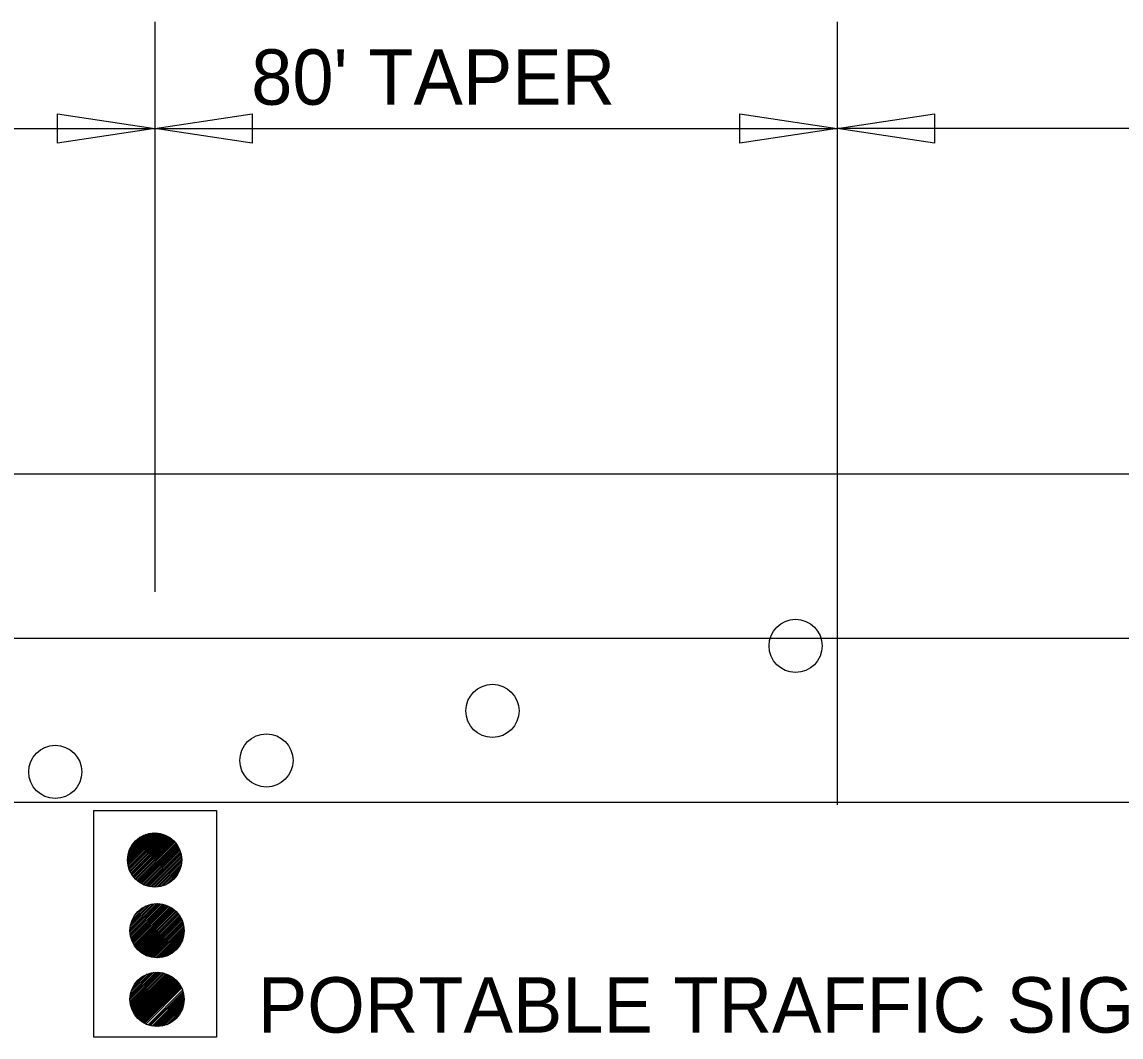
# Model space of a CAD drawing. Extents: x 1930579 to 1939784, y 596179 to 597522.
# Drawn here: x 1938170.6 to 1938289.6, y 596880.5 to 596990.5 of the extents above; entities that cross this region are included whole.
import ezdxf

# ---------------------------------------------------------------- set-up
doc = ezdxf.new("R2010")
doc.units = 0
doc.layers.add('Default', color=7, linetype='Continuous')

msp = doc.modelspace()

# ---------------------------------------------------------------- linework, layer by layer
at = {"layer": 'Default'}
for p, q in [((1938184.94, 596990.46), (1938184.94, 596928.7)), ((1938258.87, 596990.46), (1938258.87, 596928.7)), ((1938174.39, 596977.33), (1938174.39, 596980.5)), ((1938174.39, 596980.5), (1938184.94, 596978.92)), ((1938184.94, 596978.92), (1938195.48, 596980.5)), ((1938195.48, 596980.5), (1938195.48, 596977.33)), ((1938248.33, 596977.33), (1938248.33, 596980.5)), ((1938248.33, 596980.5), (1938258.87, 596978.92)), ((1938258.87, 596978.92), (1938269.42, 596980.5)), ((1938269.42, 596980.5), (1938269.42, 596977.33)), ((1938134.27, 596978.92), (1938184.94, 596978.92)), ((1938184.94, 596978.92), (1938174.39, 596977.33)), ((1938184.94, 596978.92), (1938258.87, 596978.92)), ((1938195.48, 596977.33), (1938184.94, 596978.92)), ((1938258.87, 596978.92), (1938248.33, 596977.33)), ((1938269.42, 596977.33), (1938258.87, 596978.92)), ((1938703.26, 596978.92), (1938258.87, 596978.92)), ((1938258.87, 596957.84), (1938258.87, 596905.62)), ((1937601.26, 596941.48), (1938703.26, 596941.48)), ((1937499.1, 596923.69), (1938703.26, 596923.69)), ((1937601.26, 596905.9), (1938703.26, 596905.9)), ((1938181.98, 596899.52), (1938185.06, 596902.59)), ((1938181.98, 596899.69), (1938184.88, 596902.59)), ((1938181.99, 596899.35), (1938185.22, 596902.58)), ((1938181.99, 596899.88), (1938184.69, 596902.58)), ((1938182.01, 596900.09), (1938184.48, 596902.56)), ((1938182.02, 596899.19), (1938185.38, 596902.56)), ((1938182.04, 596899.04), (1938185.54, 596902.53)), ((1938182.05, 596900.31), (1938184.26, 596902.52)), ((1938182.08, 596898.89), (1938185.68, 596902.49)), ((1938182.12, 596898.75), (1938185.82, 596902.45)), ((1938182.12, 596900.56), (1938184.01, 596902.45)), ((1938182.17, 596898.62), (1938185.96, 596902.41)), ((1938182.22, 596898.49), (1938186.08, 596902.35)), ((1938182.24, 596900.86), (1938183.72, 596902.34)), ((1938182.28, 596898.36), (1938186.21, 596902.3)), ((1938182.34, 596898.24), (1938186.33, 596902.23)), ((1938182.4, 596898.13), (1938186.44, 596902.17)), ((1938182.45, 596901.25), (1938183.32, 596902.12)), ((1938182.47, 596898.02), (1938186.55, 596902.1)), ((1938182.55, 596897.91), (1938186.66, 596902.02)), ((1938182.63, 596897.81), (1938186.76, 596901.95)), ((1938182.71, 596897.71), (1938186.86, 596901.86)), ((1938182.8, 596897.62), (1938186.95, 596901.78)), ((1938182.89, 596897.53), (1938187.05, 596901.69)), ((1938182.98, 596897.44), (1938187.13, 596901.59)), ((1938183.08, 596897.36), (1938187.21, 596901.49)), ((1938183.18, 596897.28), (1938187.29, 596901.39)), ((1938183.29, 596897.2), (1938187.37, 596901.28)), ((1938183.4, 596897.13), (1938187.44, 596901.17)), ((1938183.51, 596897.07), (1938187.5, 596901.06)), ((1938183.63, 596897.01), (1938187.56, 596900.94)), ((1938183.76, 596896.95), (1938187.62, 596900.82)), ((1938183.89, 596896.9), (1938187.67, 596900.69)), ((1938184.02, 596896.85), (1938187.72, 596900.55)), ((1938184.16, 596896.81), (1938187.76, 596900.41)), ((1938184.31, 596896.78), (1938187.8, 596900.27)), ((1938184.46, 596896.75), (1938187.83, 596900.11)), ((1938184.62, 596896.73), (1938187.85, 596899.95)), ((1938184.79, 596896.71), (1938187.86, 596899.79)), ((1938184.96, 596896.71), (1938187.86, 596899.61)), ((1938185.15, 596896.72), (1938187.85, 596899.42)), ((1938185.36, 596896.74), (1938187.83, 596899.21)), ((1938185.58, 596896.79), (1938187.79, 596898.99)), ((1938185.83, 596896.86), (1938187.72, 596898.74)), ((1938186.13, 596896.97), (1938187.6, 596898.44)), ((1938186.53, 596897.19), (1938187.38, 596898.05)), ((1938182.25, 596891.86), (1938185.32, 596894.93)), ((1938182.25, 596892.04), (1938185.15, 596894.93)), ((1938182.26, 596892.23), (1938184.96, 596894.93)), ((1938182.26, 596891.69), (1938185.49, 596894.92)), ((1938182.28, 596891.53), (1938185.65, 596894.9)), ((1938182.28, 596892.43), (1938184.75, 596894.9)), ((1938182.31, 596891.38), (1938185.81, 596894.87)), ((1938182.32, 596892.65), (1938184.53, 596894.86)), ((1938182.35, 596891.23), (1938185.95, 596894.83)), ((1938182.39, 596891.09), (1938186.09, 596894.79)), ((1938182.39, 596892.9), (1938184.28, 596894.79)), ((1938182.44, 596890.96), (1938186.23, 596894.75)), ((1938182.49, 596890.83), (1938186.35, 596894.69)), ((1938182.51, 596893.2), (1938183.98, 596894.68)), ((1938182.54, 596890.7), (1938186.48, 596894.64)), ((1938182.61, 596890.59), (1938186.6, 596894.58)), ((1938182.67, 596890.47), (1938186.71, 596894.51)), ((1938182.72, 596893.59), (1938183.59, 596894.46)), ((1938182.74, 596890.36), (1938186.82, 596894.44)), ((1938182.82, 596890.25), (1938186.93, 596894.37)), ((1938182.9, 596890.15), (1938187.03, 596894.29)), ((1938182.98, 596890.05), (1938187.13, 596894.2)), ((1938183.06, 596889.96), (1938187.22, 596894.12)), ((1938183.16, 596889.87), (1938187.31, 596894.03)), ((1938183.25, 596889.78), (1938187.4, 596893.93)), ((1938183.35, 596889.7), (1938187.48, 596893.83)), ((1938183.45, 596889.62), (1938187.56, 596893.73)), ((1938183.56, 596889.55), (1938187.64, 596893.63)), ((1938183.67, 596889.48), (1938187.71, 596893.51)), ((1938183.78, 596889.41), (1938187.77, 596893.4)), ((1938183.9, 596889.35), (1938187.83, 596893.28)), ((1938184.03, 596889.29), (1938187.89, 596893.16)), ((1938184.15, 596889.24), (1938187.94, 596893.03)), ((1938184.29, 596889.19), (1938187.99, 596892.89)), ((1938184.43, 596889.15), (1938188.03, 596892.75)), ((1938184.57, 596889.12), (1938188.07, 596892.61)), ((1938184.73, 596889.09), (1938188.09, 596892.46)), ((1938184.89, 596889.07), (1938188.12, 596892.3)), ((1938185.06, 596889.05), (1938188.13, 596892.13)), ((1938185.23, 596889.05), (1938188.13, 596891.95)), ((1938185.42, 596889.06), (1938188.12, 596891.76)), ((1938185.63, 596889.08), (1938188.1, 596891.55)), ((1938185.85, 596889.13), (1938188.06, 596891.33)), ((1938186.1, 596889.2), (1938187.99, 596891.08)), ((1938186.4, 596889.31), (1938187.87, 596890.79)), ((1938186.8, 596889.53), (1938187.65, 596890.39)), ((1938182.25, 596884.52), (1938185.23, 596887.5)), ((1938182.25, 596884.7), (1938185.04, 596887.49)), ((1938182.26, 596884.34), (1938185.4, 596887.49)), ((1938182.27, 596884.9), (1938184.85, 596887.48)), ((1938182.27, 596884.18), (1938185.56, 596887.47)), ((1938182.3, 596884.02), (1938185.72, 596887.45)), ((1938182.3, 596885.11), (1938184.63, 596887.44)), ((1938182.33, 596883.87), (1938185.87, 596887.42)), ((1938182.36, 596885.35), (1938184.39, 596887.39)), ((1938182.37, 596883.73), (1938186.01, 596887.38)), ((1938182.41, 596883.59), (1938186.15, 596887.33)), ((1938182.45, 596885.62), (1938184.12, 596887.3)), ((1938182.46, 596883.46), (1938186.28, 596887.28)), ((1938182.51, 596883.33), (1938186.41, 596887.23)), ((1938182.57, 596883.21), (1938186.53, 596887.17)), ((1938182.6, 596885.96), (1938183.79, 596887.14)), ((1938182.64, 596883.09), (1938186.65, 596887.11)), ((1938182.7, 596882.98), (1938186.76, 596887.04)), ((1938182.78, 596882.87), (1938186.87, 596886.97)), ((1938182.85, 596882.77), (1938186.97, 596886.89)), ((1938182.93, 596882.67), (1938187.08, 596886.81)), ((1938183.02, 596882.57), (1938187.17, 596886.73)), ((1938183.1, 596882.48), (1938187.26, 596886.64)), ((1938183.2, 596882.39), (1938187.35, 596886.55)), ((1938183.29, 596882.31), (1938187.44, 596886.45)), ((1938183.39, 596882.22), (1938187.52, 596886.35)), ((1938183.5, 596882.15), (1938187.6, 596886.25)), ((1938183.61, 596882.08), (1938187.67, 596886.14)), ((1938183.72, 596882.01), (1938187.74, 596886.03)), ((1938183.83, 596881.94), (1938187.8, 596885.91)), ((1938183.96, 596881.88), (1938187.86, 596885.79)), ((1938184.21, 596881.78), (1938187.96, 596885.53)), ((1938184.35, 596881.73), (1938188.01, 596885.39)), ((1938184.49, 596881.7), (1938188.05, 596885.25)), ((1938184.64, 596881.66), (1938188.08, 596885.1)), ((1938184.8, 596881.64), (1938188.1, 596884.95)), ((1938184.96, 596881.62), (1938188.12, 596884.78)), ((1938185.13, 596881.61), (1938188.13, 596884.61)), ((1938185.32, 596881.61), (1938188.13, 596884.43)), ((1938185.51, 596881.63), (1938188.11, 596884.23)), ((1938185.72, 596881.66), (1938188.08, 596884.02)), ((1938185.96, 596881.71), (1938188.03, 596883.79)), ((1938186.23, 596881.8), (1938187.94, 596883.52)), ((1938186.55, 596881.95), (1938187.8, 596883.19)), ((1938187.13, 596882.34), (1938187.4, 596882.62))]:
    msp.add_line(p, q, dxfattribs=at)
msp.add_lwpolyline([(1938178.34, 596905.01), (1938191.64, 596905.01), (1938191.64, 596880.47), (1938178.34, 596880.47)], close=True, dxfattribs=at)
for centre, radius in [((1938254.38, 596922.85), 2.88), ((1938221.53, 596915.81), 2.88), ((1938197.04, 596910.44), 2.88), ((1938174.16, 596909.2), 2.88), ((1938184.92, 596899.65), 2.94), ((1938185.19, 596891.99), 2.94), ((1938185.19, 596884.55), 2.94)]:
    msp.add_circle(centre, radius, dxfattribs=at)

# ---------------------------------------------------------------- texts
for s, height, p in [("80' TAPER", 6, (1938195.39, 596981.49)), ('PORTABLE TRAFFIC SIGNAL SYSTEM', 5.9996, (1938196.11, 596880.95))]:
    msp.add_text(s, height=height, rotation=360, dxfattribs=at).set_placement(p)

doc.saveas('drawing.dxf')
